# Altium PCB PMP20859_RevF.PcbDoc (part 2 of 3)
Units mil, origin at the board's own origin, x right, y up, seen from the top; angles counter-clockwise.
Board outline 5000 x 4200 mil, 4 copper layers (Top Layer, Signal Layer 1, Signal Layer 2, Bottom Layer), stack 61.2 mil thick; 264 components, 163 nets, 897 pads, 223 vias.
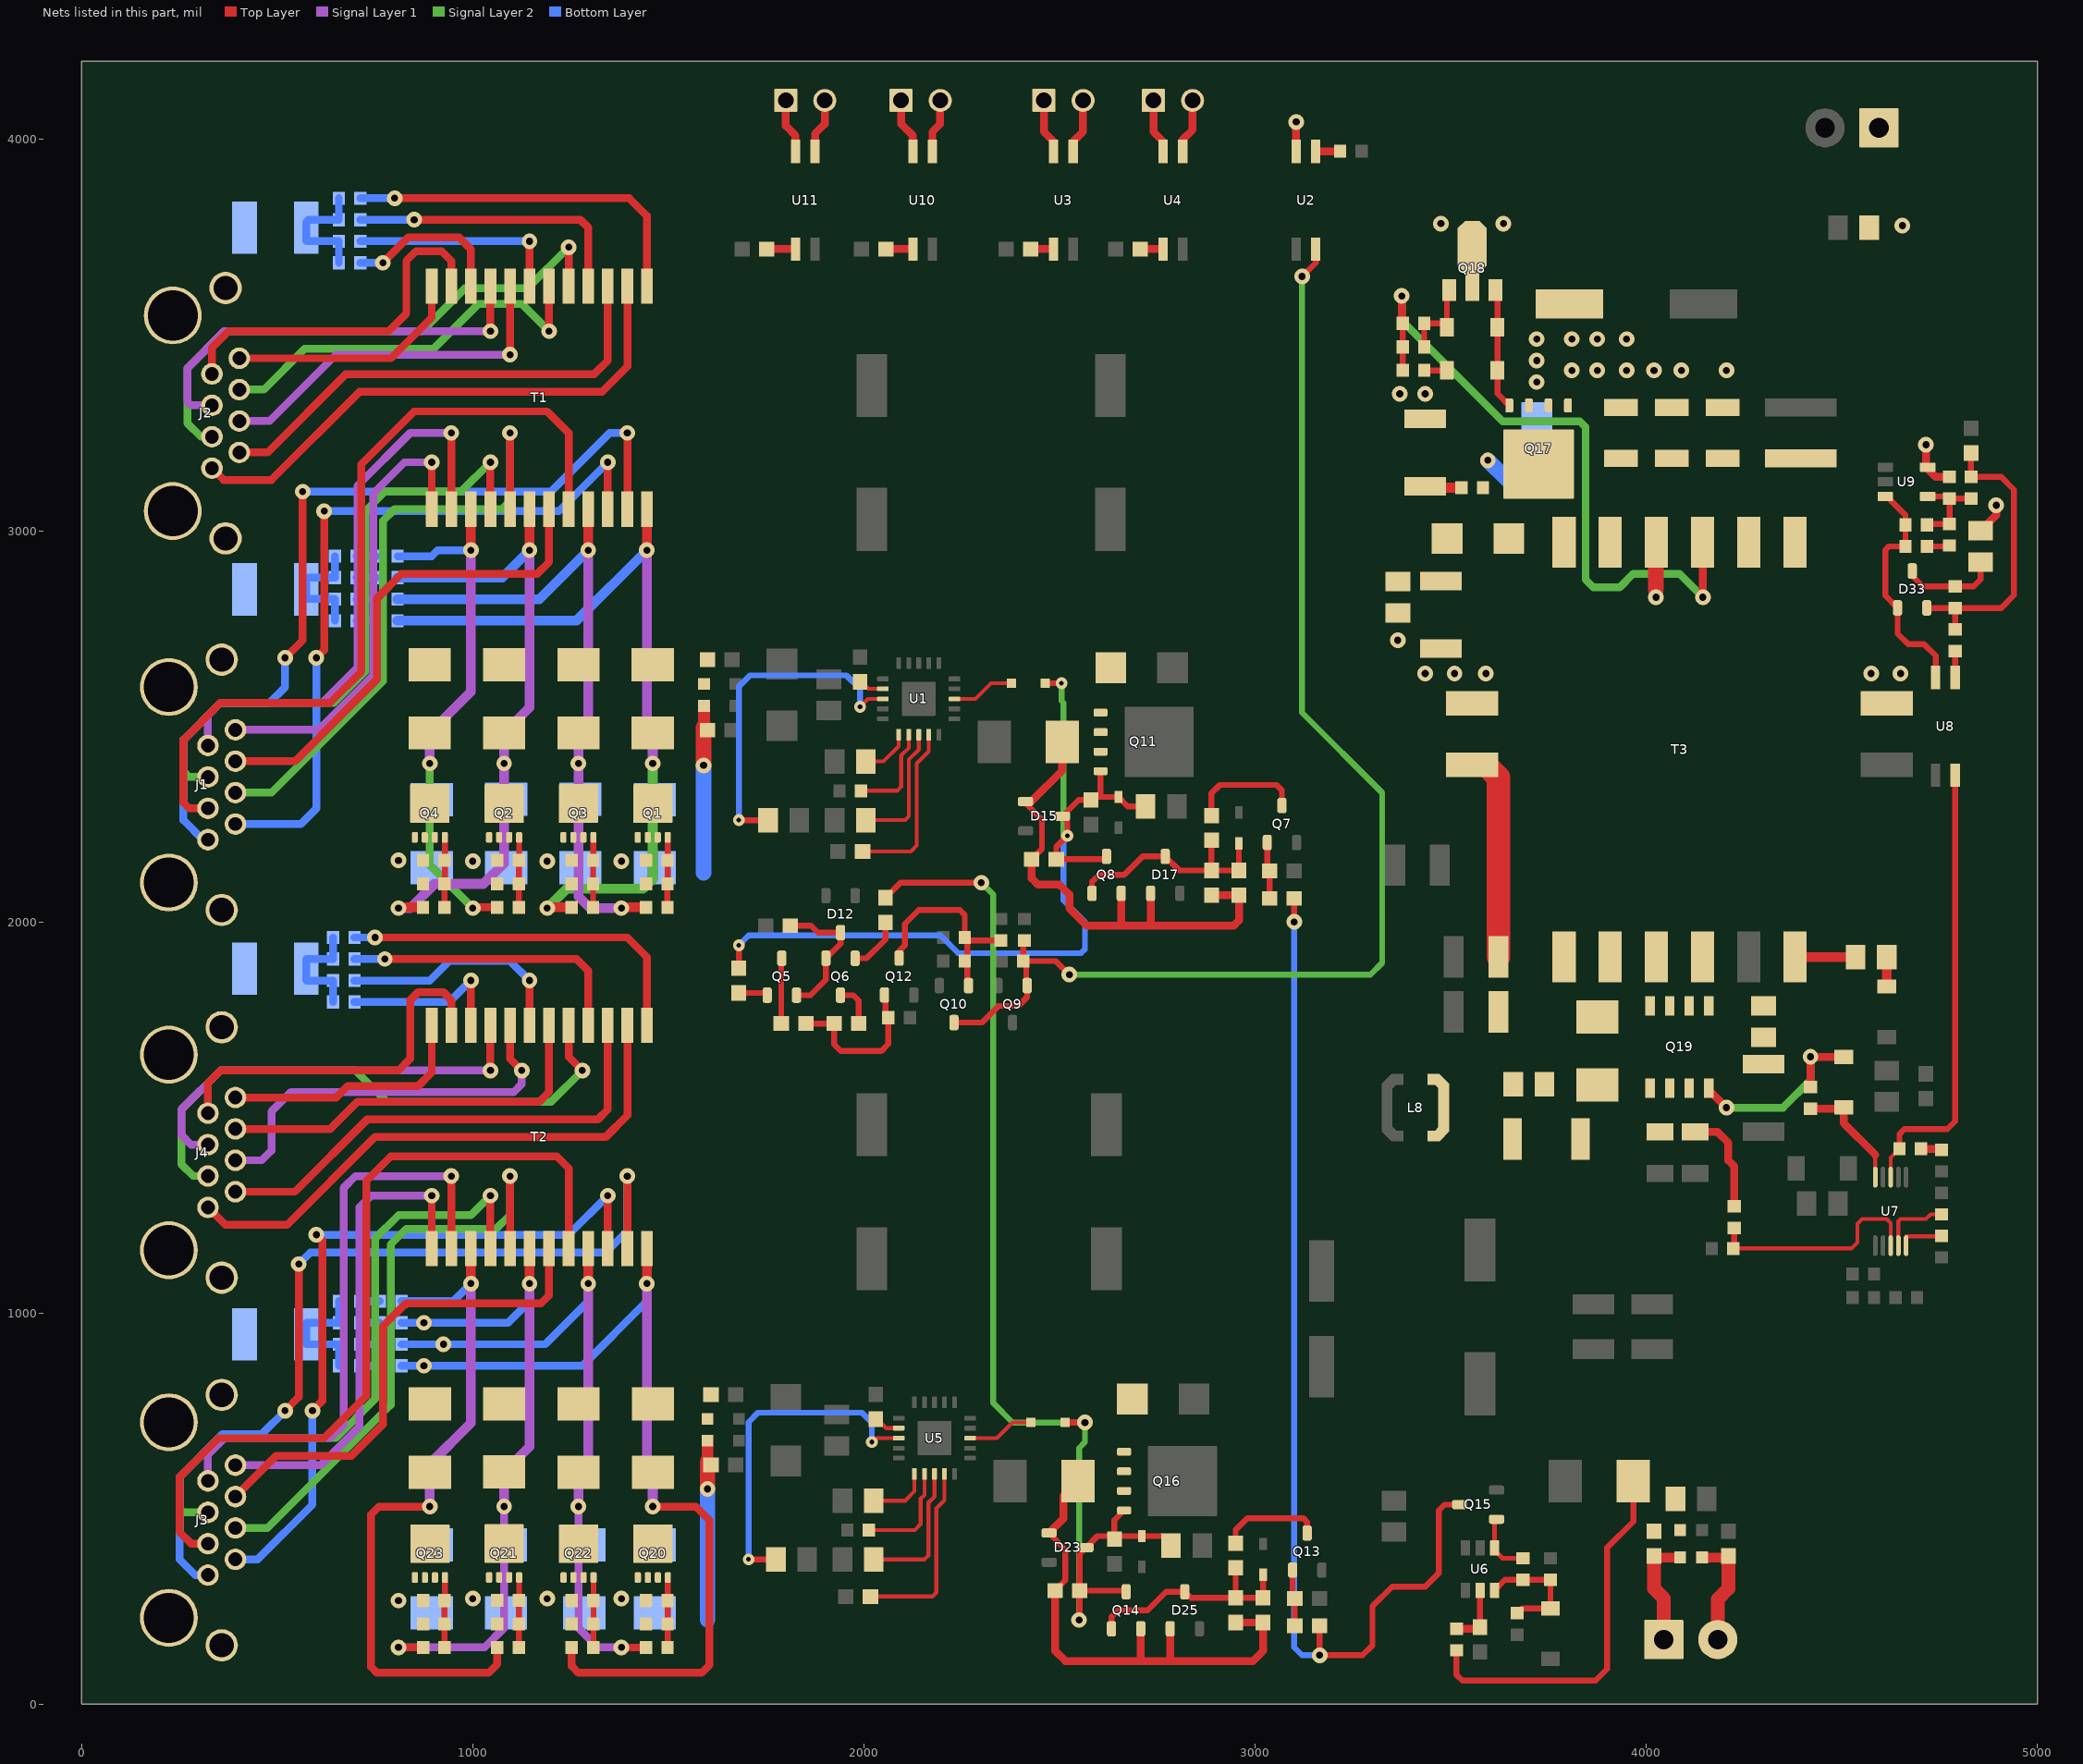
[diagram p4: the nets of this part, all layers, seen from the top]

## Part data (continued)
Q8 Q9 Q10 Q12 Q14 Q15: library part CMP-0000947-2, "MOSFET, N-CH, 100 V, 0.17 A, SOT-23", Alternate Manufacturer=None, Manufacturer="Fairchild Semiconductor", Supplier Part Number 1=BSS123NCT-ND, Value1=1, Value2="1.8 nC"
Q11 Q16: library part CMP-0000962-2, "MOSFET, N-CH, 100 V, 10 A, DQJ0008A (VSONP-8)", Alternate Manufacturer=None, Manufacturer="Texas Instruments", Value2="17 nC"
Q17: library part CMP-0000708-1, "MOSFET, N-CH, 40 V, 15 A, DQJ0008A (VSONP-8)", Alternate Manufacturer=None, Manufacturer="Texas Instruments", Supplier Part Number 1=296-30572-1-ND, Value1=0.009, Value2="7.7 nC"
Q18: library part CMP-0000356-2, "Transistor, PNP, 60 V, 0.6 A, AEC-Q101, SOT-89", Manufacturer="Diodes Inc.", Supplier Part Number 1=DXT2907ADICT-ND, Value1="0.6 A", Value2=300
Q19: library part CMP-0001058-1, "MOSFET, N-CH, 150 V, 4.6 A, PQFN08A", Alternate Manufacturer=None, Manufacturer="Fairchild Semiconductor", Supplier Part Number 1=FDMS86252CT-ND, Value1=0, Value2="11 nC"
R1 R2 R7 R12 R13 R14 R15 R16 R17 R18 R23 R28 R29 R30 R31 R32: library part CMP-0022590-4, "RES, 75.0, 1%, 0.1 W, AEC-Q200 Grade 0, 0603", Manufacturer=Vishay-Dale, PartNumber=CRCW060375R0FKEA, Power_W=100mW, Supplier Part Number 1=541-75.0HCT-ND, TempCo="100 ppm/C", Tolerance_%=1%, Value2=0.1W, Value_Code=75R0, ValueDisplayed=75.0
R3 R4 R5 R6 R19 R20 R21 R22: library part CMP-0022138-4, "RES, 1.00 M, 1%, 0.1 W, AEC-Q200 Grade 0, 0603", Manufacturer=Vishay-Dale, PartNumber=CRCW06031M00FKEA, Power_W=100mW, Supplier Part Number 1=541-1.00MHCT-ND, TempCo="100 ppm/C", Tolerance_%=1%, Value2=0.1W, Value_Code=1M00, ValueDisplayed=1.00M
R8 R9 R10 R11 R24 R25 R26 R27: library part CMP-0022224-4, "RES, 232 k, 1%, 0.1 W, AEC-Q200 Grade 0, 0603", Manufacturer=Vishay-Dale, PartNumber=CRCW0603232KFKEA, Power_W=100mW, Supplier Part Number 1=541-232KHCT-ND, TempCo="100 ppm/C", Tolerance_%=1%, Value2=0.1W, Value_Code=232k
R33 R74: library part CMP-0022204-4, "RES, 20.0 k, 1%, 0.1 W, AEC-Q200 Grade 0, 0603", Manufacturer=Vishay-Dale, PartNumber=CRCW060320K0FKEA, Power_W=100mW, Supplier Part Number 1=541-20.0KHCT-ND, TempCo="100 ppm/C", Tolerance_%=1%, Value2=0.1W, Value_Code=20k0, ValueDisplayed=20.0k
R34 R53 R55 R57 R69 R96 R97: library part CMP-0021998-4, "RES, 10.0 k, 1%, 0.1 W, AEC-Q200 Grade 0, 0603", Manufacturer=Vishay-Dale, PartNumber=CRCW060310K0FKEA, Power_W=100mW, Supplier Part Number 1=541-10.0KHCT-ND, TempCo="100 ppm/C", Tolerance_%=1%, Value2=0.1W, Value_Code=10k0, ValueDisplayed=10.0k
R35 R62: library part CMP-0022254-4, "RES, 27.4 k, 1%, 0.1 W, AEC-Q200 Grade 0, 0603", Manufacturer=Vishay-Dale, PartNumber=CRCW060327K4FKEA, Power_W=100mW, Supplier Part Number 1=541-27.4KHCT-ND, TempCo="100 ppm/C", Tolerance_%=1%, Value2=0.1W, Value_Code=27k4, ValueDisplayed=27.4k
R36 R38 R58 R59: library part CMP-0023050-5, "RES, 35.7 k, 1%, 0.1 W, 0603", Manufacturer=Yageo, Power_W=100mW, Supplier Part Number 1=311-35.7KHRCT-ND, TempCo="100 ppm/C", Tolerance_%=1%, Value2=0.1W, Value_Code=35k7, ValueDisplayed=35.7k
R37 R40 R41 R43 R61 R66 R76 R82: library part CMP-0021990-4, "RES, 100 k, 1%, 0.1 W, AEC-Q200 Grade 0, 0603", Manufacturer=Vishay-Dale, PartNumber=CRCW0603100KFKEA, Power_W=100mW, Supplier Part Number 1=541-100KHCT-ND, TempCo="100 ppm/C", Tolerance_%=1%, Value2=0.1W, Value_Code=100k
R39 R65: library part CMP-0022040-4, "RES, 137 k, 1%, 0.1 W, AEC-Q200 Grade 0, 0603", Manufacturer=Vishay-Dale, PartNumber=CRCW0603137KFKEA, Power_W=100mW, Supplier Part Number 1=541-137KHCT-ND, TempCo="100 ppm/C", Tolerance_%=1%, Value2=0.1W, Value_Code=137k
R42 R67: library part CMP-0022532-4, "RES, 60.4 k, 1%, 0.1 W, AEC-Q200 Grade 0, 0603", Manufacturer=Vishay-Dale, Power_W=100mW, Supplier Part Number 1=541-60.4KHCT-ND, TempCo="100 ppm/C", Tolerance_%=1%, Value2=0.1W, Value_Code=60k4, ValueDisplayed=60.4k
R44 R45: library part CMP-0022133-4, "RES, 1.78 k, 1%, 0.1 W, AEC-Q200 Grade 0, 0603", Manufacturer=Vishay-Dale, PartNumber=CRCW06031K78FKEA, Power_W=100mW, Supplier Part Number 1=541-1.78KHCT-ND, TempCo="100 ppm/C", Tolerance_%=1%, Value2=0.1W, Value_Code=1k78, ValueDisplayed=1.78k
R47 R71: library part CMP-0021376-3, "RES, 63.4, 1%, 0.125 W, AEC-Q200 Grade 0, 0805", Manufacturer=Vishay-Dale, PartNumber=CRCW080563R4FKEA, Power_W=125mW, Supplier Part Number 1=541-63.4CCT-ND, TempCo="100 ppm/C", Tolerance_%=1%, Value2=0.125W, Value_Code=63R4, ValueDisplayed=63.4
R48 R72: library part CMP-0020959-3, "RES, 1.21 k, 1%, 0.125 W, AEC-Q200 Grade 0, 0805", Manufacturer=Vishay-Dale, Power_W=125mW, Supplier Part Number 1=541-1.21KCCT-ND, TempCo="100 ppm/C", Tolerance_%=1%, Value2=0.125W, Value_Code=1k21, ValueDisplayed=1.21k
R49 R52: library part CMP-0022426-4, "RES, 44.2 k, 1%, 0.1 W, AEC-Q200 Grade 0, 0603", Manufacturer=Vishay-Dale, PartNumber=CRCW060344K2FKEA, Power_W=100mW, Supplier Part Number 1=541-44.2KHCT-ND, TempCo="100 ppm/C", Tolerance_%=1%, Value2=0.1W, Value_Code=44k2, ValueDisplayed=44.2k
R50 R70: library part CMP-0020476-3, "RES, 1.3 k, 5%, 0.125 W, AEC-Q200 Grade 0, 0805", Manufacturer=Vishay-Dale, PartNumber=CRCW08051K30JNEA, Power_W=125mW, Supplier Part Number 1=541-1.3KACT-ND, TempCo="200 ppm/C", Tolerance_%=5%, Value2=0.125W, Value_Code=1k30, ValueDisplayed=1.3k
R54 R75: library part CMP-0022447-4, "RES, 49.9 k, 1%, 0.1 W, AEC-Q200 Grade 0, 0603", Manufacturer=Vishay-Dale, PartNumber=CRCW060349K9FKEA, Power_W=100mW, Supplier Part Number 1=541-49.9KHCT-ND, TempCo="100 ppm/C", Tolerance_%=1%, Value2=0.1W, Value_Code=49k9, ValueDisplayed=49.9k
R56 R98: library part CMP-0022109-5, "RES, 1.00 k, 1%, 0.1 W, AEC-Q200 Grade 0, 0603", Manufacturer=Vishay-Dale, PartNumber=CRCW06031K00FKEA, Power_W=100mW, Supplier Part Number 1=541-1.00KHCT-ND, TempCo="100 ppm/C", Tolerance_%=1%, Value2=0.1W, Value_Code=1k00, ValueDisplayed=1.00k
R60: library part CMP-0021998-4, "RES, 10.0 k, 1%, 0.1 W, AEC-Q200 Grade 0, 0603", Manufacturer=Vishay-Dale, Power_W=100mW, Supplier Part Number 1=541-10.0KHCT-ND, TempCo="100 ppm/C", Tolerance_%=1%, Value2=0.1W, Value_Code=10k0, ValueDisplayed=10.0k
R77: library part CMP-0022110-4, "RES, 1.02 k, 1%, 0.1 W, AEC-Q200 Grade 0, 0603", Manufacturer=Vishay-Dale, PartNumber=CRCW06031K02FKEA, Power_W=100mW, Supplier Part Number 1=541-1.02KHCT-ND, TempCo="100 ppm/C", Tolerance_%=1%, Value2=0.1W, Value_Code=1k02, ValueDisplayed=1.02k
R78: library part CMP-0016116-3, "RES, 30 k, 5%, 0.75 W, AEC-Q200 Grade 0, 2010", Manufacturer=Vishay-Dale, PartNumber=CRCW201030K0JNEF, Power_W=750mW, Supplier Part Number 1=541-30KWCT-ND, TempCo="200 ppm/C", Tolerance_%=5%, Value2=0.75W, Value_Code=30k0, ValueDisplayed=30k
R79: library part CMP-0016106-3, "RES, 2.0 k, 5%, 0.75 W, AEC-Q200 Grade 0, 2010", Manufacturer=Vishay-Dale, PartNumber=CRCW20102K00JNEF, Power_W=750mW, Supplier Part Number 1=541-2.0KWCT-ND, TempCo="200 ppm/C", Tolerance_%=5%, Value2=0.75W, Value_Code=2k00, ValueDisplayed=2.0k
R80: library part CMP-0025821-4, "RES, 4.7, 5%, 0.1 W, AEC-Q200 Grade 0, 0603", Manufacturer=Vishay-Dale, PartNumber=CRCW06034R70JNEA, Power_W=100mW, Supplier Part Number 1=541-4.7GCT-ND, TempCo="200 ppm/C", Tolerance_%=5%, Value2=0.1W, Value_Code=4R70, ValueDisplayed=4.7
R81: library part CMP-0020497-3, "RES, 20, 5%, 0.125 W, AEC-Q200 Grade 0, 0805", Manufacturer=Vishay-Dale, PartNumber=CRCW080520R0JNEA, Power_W=125mW, Supplier Part Number 1=541-20ACT-ND, TempCo="200 ppm/C", Tolerance_%=5%, Value2=0.125W, Value_Code=20R0, ValueDisplayed=20
R84: library part CMP-0022458-4, "RES, 4.99 k, 1%, 0.1 W, AEC-Q200 Grade 0, 0603", Manufacturer=Vishay-Dale, PartNumber=CRCW06034K99FKEA, Power_W=100mW, Supplier Part Number 1=541-4.99KHCT-ND, TempCo="100 ppm/C", Tolerance_%=1%, Value2=0.1W, Value_Code=4k99, ValueDisplayed=4.99k
R85: library part CMP-0016136-3, "RES, 3.3, 5%, 0.75 W, AEC-Q200 Grade 0, 2010", Manufacturer=Vishay-Dale, PartNumber=CRCW20103R30JNEF, Power_W=750mW, Supplier Part Number 1=541-3.3WCT-ND, TempCo="200 ppm/C", Tolerance_%=5%, Value2=0.75W, Value_Code=3R30, ValueDisplayed=3.3
R86: library part CMP-0022381-4, "RES, 3.83 k, 1%, 0.1 W, AEC-Q200 Grade 0, 0603", Manufacturer=Vishay-Dale, PartNumber=CRCW06033K83FKEA, Power_W=100mW, Supplier Part Number 1=541-3.83KHCT-ND, TempCo="100 ppm/C", Tolerance_%=1%, Value2=0.1W, Value_Code=3k83, ValueDisplayed=3.83k
R87: library part CMP-0022242-4, "RES, 25.5 k, 1%, 0.1 W, AEC-Q200 Grade 0, 0603", Manufacturer=Vishay-Dale, PartNumber=CRCW060325K5FKEA, Power_W=100mW, Supplier Part Number 1=541-25.5KHCT-ND, TempCo="100 ppm/C", Tolerance_%=1%, Value2=0.1W, Value_Code=25k5, ValueDisplayed=25.5k
R88: library part CMP-0022448-4, "RES, 49.9, 1%, 0.1 W, AEC-Q200 Grade 0, 0603", Manufacturer=Vishay-Dale, PartNumber=CRCW060349R9FKEA, Power_W=100mW, Supplier Part Number 1=541-49.9HCT-ND, TempCo="100 ppm/C", Tolerance_%=1%, Value2=0.1W, Value_Code=49R9, ValueDisplayed=49.9
R89: library part CMP-0022588-5, "RES, 750, 1%, 0.1 W, AEC-Q200 Grade 0, 0603", Manufacturer=Vishay-Dale, PartNumber=CRCW0603750RFKEA, Power_W=100mW, Supplier Part Number 1=541-750HCT-ND, TempCo="100 ppm/C", Tolerance_%=1%, Value2=0.1W, Value_Code=750R, ValueDisplayed=750
R90: library part CMP-0016178-3, "RES, 75, 5%, 0.75 W, AEC-Q200 Grade 0, 2010", Manufacturer=Vishay-Dale, PartNumber=CRCW201075R0JNEF, Power_W=750mW, Supplier Part Number 1=541-75.0WCT-ND, TempCo="200 ppm/C", Tolerance_%=5%, Value2=0.75W, Value_Code=75R0, ValueDisplayed=75
R91: library part CMP-0022337-5, "RES, 332, 1%, 0.1 W, AEC-Q200 Grade 0, 0603", Manufacturer=Vishay-Dale, PartNumber=CRCW0603332RFKEA, Power_W=100mW, Supplier Part Number 1=541-332HCT-ND, TempCo="100 ppm/C", Tolerance_%=1%, Value2=0.1W, Value_Code=332R, ValueDisplayed=332
R92: library part CMP-0025697-4, "RES, 0, 5%, 0.1 W, AEC-Q200 Grade 0, 0603", Manufacturer=Vishay-Dale, PartNumber=CRCW06030000Z0EA, Power_W=100mW, Supplier Part Number 1=541-0.0GCT-ND, TempCo="200 ppm/C", Tolerance_%=5%, Value2=0.1W, Value_Code=0000, ValueDisplayed=0
R93 R94: library part CMP-0017787-2, "RES, 0.27, 1%, 0.25 W, 1206", Manufacturer=Panasonic, PartNumber=ERJ-8RQFR27V, Power_W=250mW, Supplier Part Number 1=P.27RCT-ND, TempCo="250 ppm/C", Tolerance_%=1%, Value2=0.25W, Value_Code=R270, ValueDisplayed=0.27
R95: library part CMP-0022547-5, "RES, 665, 1%, 0.1 W, AEC-Q200 Grade 0, 0603", Manufacturer=Vishay-Dale, PartNumber=CRCW0603665RFKEA, Power_W=100mW, Supplier Part Number 1=541-665HCT-ND, TempCo="100 ppm/C", Tolerance_%=1%, Value2=0.1W, Value_Code=665R, ValueDisplayed=665
R99: library part CMP-0022374-4, "RES, 3.24 k, 1%, 0.1 W, AEC-Q200 Grade 0, 0603", Manufacturer=Vishay-Dale, PartNumber=CRCW06033K24FKEA, Power_W=100mW, Supplier Part Number 1=541-3.24KHCT-ND, TempCo="100 ppm/C", Tolerance_%=1%, Value2=0.1W, Value_Code=3k24, ValueDisplayed=3.24k
R100 R101: library part CMP-0022324-4, "RES, 30.1 k, 1%, 0.1 W, AEC-Q200 Grade 0, 0603", Manufacturer=Vishay-Dale, PartNumber=CRCW060330K1FKEA, Power_W=100mW, Supplier Part Number 1=541-30.1KHCT-ND, TempCo="100 ppm/C", Tolerance_%=1%, Value2=0.1W, Value_Code=30k1, ValueDisplayed=30.1k
T1 T2: library part CMP-0030597-1, "Transformer, 350 uH, SMT", Manufacturer="Wurth Elektronik", ValueDisplayed=350uH
T3: library part CMP-0030440-2, "Transformer, 35 uH, SMT", Manufacturer="Pulse Engineering", ValueDisplayed=35uH
U1 U5: library part CMP-0013755-3, "IEEE 802.3bt PoE High-Power PD Interface with Automatic MPS & Autoclass, RGW0020B (VQFN-20)", Alternate Manufacturer="Texas Instruments", Alternate PartNumber=TPS2372-3RGWT, Operating Temperature Range="-40 to 125 C"
U2 U3 U4 U8 U10 U11: library part CMP-0006164-3, "Optocoupler, 3.75 kV, 80-160% CTR, SMT", Manufacturer="Fairchild Semiconductor", Supplier Part Number 1=HMHA2801A-ND, Voltage_Isolation_Vrms=3.75kV
U6: library part CMP-0032355-1, "Low Quiescent Current, Programmable-Delay Supervisory Circuit, 1 Supply Monitored, -40 to 125 degC, 6-pin SOT-23 (DBV), Green (RoHS & no Sb/Br)", Manufacturer="Texas Instruments", Rating=Catalog, Threshold Voltage 1 (typ)(Typ)(V)=Adjustable
U7: library part CMP-0066105-1, "13-100V Wide Vin, Current Mode PWM Boost Controller, DGS0010A (VSSOP-10)", Alternate Manufacturer="Texas Instruments"
U9: library part CMP-0032952-1, "Low Voltage Adjustable Precision Shunt Regulator, 39 ppm / degC, 15 mA, -40 to 85 degC, 5-pin SOT-23 (DBV), Green (RoHS & no Sb/Br)", Manufacturer="Texas Instruments", Rating=Catalog, Temp Coeff(Max)(ppm/ degree C)=129, Temp Coeff(Typ)(ppm/ degree C)=39

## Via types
v1: diameter 40, hole 18, Top Layer to Bottom Layer, 185 vias
v2: diameter 30, hole 12, Top Layer to Bottom Layer, 28 vias
v3: diameter 19.68, hole 7.87, Top Layer to Bottom Layer, 10 vias

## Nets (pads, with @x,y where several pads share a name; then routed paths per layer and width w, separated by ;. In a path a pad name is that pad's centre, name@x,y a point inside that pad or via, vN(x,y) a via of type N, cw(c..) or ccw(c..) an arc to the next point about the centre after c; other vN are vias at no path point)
AUX: C32.1 C33.1 D18.2 L5.2 R76.2 | length 973.8
  Top Layer w15: R76.2@3515,137.44 3515,75 3530,60 3870,60 3900,90 3900,400 3967.01,467.01 D18.2@3967.01,570
AUX_OUT: Q15.3 R39.2 R65.2 | length 2732.6
  Top Layer w15: v1(3100,2000) 3100.14,2000.14 R39.2@3100.14,2060 ; R65.2@3165,199.74 v1(3165,125) 3275,125 3300,150 3300,250 3350,300 3435,300 3470,335 3470,495 3485,510 Q15.3@3522.76,510
  Bottom Layer w15: v1(3100,2000) 3100,145 3120,125 v1(3165,125)
BSVG: C7.1 C12.2 C19.1 C24.2 J1.9 J1.10 J1.11 J1.12 J2.9 J2.10 J2.11 J2.12 J3.9 J3.10 J3.11 J3.12 J4.9 J4.10 J4.11 J4.12
GND: C41.2 C42.1 C43.2 C44.2 C45.2 C46.2 C50.2 C57.2 C67.2 D43.2 J5.2 J6.2 J8.1 J9.2 J10.2 Q17.1 Q17.2 Q17.3 Q18.2 Q18.4 R79.2 R85.1 R99.1 T3.10 U2.2 U3.3 U4.3 U9.5 U10.3 U11.3 | length 962.2
  Top Layer w20: U11.3@1875,3970 1875,4015 1900,4040 J10.2@1900,4100 ; U10.3@2175,3970 2175,4020 2195,4040 J9.2@2195,4100 ; U3.3@2535,3970 2535,3995 2560,4020 J5.2@2560,4100 ; U4.3@2815,3970 2815,4000 2840,4025 J6.2@2840,4100 ; U2.2@3105,3970 v1(3105,4045) ; v1@4715.51,3219.49 4715.51,3162.4 4740.35,3137.56 R99.1@4775.31,3137.56 ; C67.2@4855,3000 4895,3040 v1(4895,3065)
  Top Layer w40: 4025,2850 T3.10@4025,2969.07
  other v1: 3435,2635 3510,2635 3590,2635 4575,2635 4650,2635 3365,2720 4025,2830 4715,3220 3370,3350 3435,3350 3720,3380 3810,3410 3875,3410 3950,3410 4020,3410 4090,3410 4205,3410 3720,3435 3720,3490 3810,3490 3875,3490 3950,3490 4655,3780 3475,3785 3635,3785
NetC1_1: C1.1 D1.1 D2.1 D3.1 D4.1 L1.1
NetC1_2: C1.2 C3.2 C4.2 C5.2 C6.2 D35.2 D36.2 D37.2 D38.2 L2.1 Q1.1 Q1.2 Q1.3 Q2.1 Q2.2 Q2.3 Q3.1 Q3.2 Q3.3 Q4.1 Q4.2 Q4.3 R8.1 R9.1 R10.1 R11.1 | length 427.5
  Top Layer w30: L2.1@1591.32,2498.5 C1.2@1591.32,2552
  Top Layer w40: v1(1590,2400) 1590,2497.18 L2.1@1591.32,2498.5
  Bottom Layer w40: 1590,2125 v1(1590,2400)
  other v1: 1000,2155 1190,2155 1380,2155 810,2157.11
NetC3_1: C3.1 Q1.4 R3.2 R8.2 | length 179.3
  Top Layer w15: R3.2@1497.56,2037.11 R8.2@1497.56,2097.11 1498.39,2097.93 Q1.4@1498.39,2216.08
NetC4_1: C4.1 Q3.4 R4.2 R9.2 | length 160.1
  Top Layer w15: 1307.56,2056.28 R9.2@1307.56,2097.11 C4.1@1307.56,2157.11 1308.39,2157.93 Q3.4@1308.39,2216.08
NetC5_1: C5.1 Q2.4 R5.2 R10.2 | length 178.6
  Top Layer w15: R5.2@1118.05,2037.6 1118.05,2157.6 1118.39,2157.93 Q2.4@1118.39,2216.08
NetC6_1: C6.1 Q4.4 R6.2 R11.2 | length 179.3
  Top Layer w15: R6.2@927.56,2037.11 R11.2@927.56,2097.11 928.39,2097.93 Q4.4@928.39,2216.08
NetC7_2: C7.2 R1.1 R2.1 R7.1 R12.1 | length 328
  Bottom Layer w20: R12.1@657.44,3685 R7.1@657.44,3740 575,3740 573.74,3741.26 C7.2@573.74,3775 573.74,3788.74 580,3795 R2.1@657.44,3795 R1.1@657.44,3850
NetC8_2: C8.2 R13.2 | length 49.9
  Bottom Layer w20: R13.2@702.56,2770 C8.2@752.44,2770
NetC9_2: C9.2 R14.2 | length 49.9
  Bottom Layer w20: R14.2@702.56,2825 C9.2@752.44,2825
NetC10_2: C10.2 R15.2 | length 49.9
  Bottom Layer w20: R15.2@702.56,2880 C10.2@752.44,2880
NetC11_2: C11.2 R16.2 | length 49.9
  Bottom Layer w20: R16.2@702.56,2935 C11.2@752.44,2935
NetC12_1: C12.1 R13.1 R14.1 R15.1 R16.1 | length 307.7
  Bottom Layer w20: R14.1@646.18,2826.26 573.74,2826.26 C12.1@573.74,2850 573.74,2876.26 577.48,2880 R15.1@647.44,2880 R16.1@647.44,2935 ; R13.1@647.44,2770 R14.1@647.44,2825
NetC13_1: C13.1 D5.1 D6.1 D7.1 D8.1 L3.1
NetC13_2: C13.2 C15.2 C16.2 C17.2 C18.2 D39.2 D40.2 D41.2 D42.2 L4.1 Q20.1 Q20.2 Q20.3 Q21.1 Q21.2 Q21.3 Q22.1 Q22.2 Q22.3 Q23.1 Q23.2 Q23.3 R24.1 R25.1 R26.1 R27.1 | length 458.4
  Top Layer w30: L4.1@1600.32,619.8 C13.2@1600.32,673.3
  Top Layer w40: v1(1600,550) 1600,619.49 L4.1@1600.32,619.8
  Bottom Layer w40: 1600,215 v1(1600,550)
  other v1: 810,264.68 1000,269.68 1190,269.68 1380,269.68
NetC15_1: C15.1 Q20.4 R19.2 R24.2 | length 178.1
  Top Layer w15: R19.2@1498.71,145.51 Q20.4@1498.71,323.66
NetC16_1: C16.1 Q22.4 R20.2 R25.2 | length 178.1
  Top Layer w15: R20.2@1308.71,145.51 Q22.4@1308.71,323.66
NetC17_1: C17.1 Q21.4 R21.2 R26.2 | length 179.3
  Top Layer w15: R21.2@1117.56,145 R26.2@1117.56,205 C17.1@1117.56,265 1118.39,265.82 Q21.4@1118.39,323.97
NetC18_1: C18.1 Q23.4 R22.2 R27.2 | length 179.3
  Top Layer w15: R22.2@927.88,144.68 R27.2@927.88,204.68 C18.1@927.88,264.68 928.71,265.51 Q23.4@928.71,323.66
NetC19_2: C19.2 R17.1 R18.1 R23.1 R28.1 | length 300.9
  Bottom Layer w20: R28.1@642.44,1795 R23.1@642.44,1850 575,1850 573.74,1851.26 C19.2@573.74,1880.31 573.74,1903.74 575,1905 R18.1@642.44,1905 R17.1@642.44,1960
NetC20_2: C20.2 R29.2 | length 49.9
  Bottom Layer w20: R29.2@712.56,865 C20.2@762.44,865
NetC21_2: C21.2 R30.2 | length 49.9
  Bottom Layer w20: R30.2@712.56,920 C21.2@762.44,920
NetC22_2: C22.2 R31.2 | length 49.9
  Bottom Layer w20: R31.2@712.56,975 C22.2@762.44,975
NetC23_2: C23.2 R32.2 | length 49.9
  Bottom Layer w20: R32.2@712.56,1030 C23.2@762.44,1030
NetC24_1: C24.1 R29.1 R30.1 R31.1 R32.1 | length 330.9
  Bottom Layer w20: R29.1@657.44,865 R30.1@657.44,920 575,920 573.74,921.26 C24.1@573.74,945 573.74,973.74 575,975 R31.1@657.44,975 R32.1@657.44,1030
NetC28_1: C28.1 C68.2 D9.2 D14.2 D15.3 Q8.3 Q11.4 R37.1 R40.1 | length 2296.6
  Top Layer w15: R40.1@1680,1881.18 v2(1680,1940) ; D14.2@2463.62,2610 v2(2505,2610) ; Q11.4@2604.96,2385 2604.96,2319.41 2588.23,2319.41 R37.1@2588.19,2319.37 ; Q8.3@2613.07,2160 C28.1@2491.81,2160 2491.81,2191.81 v2(2520,2220) 2520,2257.56 D15.3@2507.56,2270 2549.06,2311.5 R37.1@2580.32,2311.5 R37.1@2588.19,2319.37 ; C68.2@2720,2295 2674.69,2295 D9.2@2650.32,2319.37 R37.1@2588.19,2319.37
  Signal Layer 2 w15: v2(2505,2610) 2505,2565 2510,2560 v2@2510,2220
  Bottom Layer w15: v2(1680,1940) 1705,1965 2195.98,1965 2240.98,1920 2555,1920 2565,1930 2565,2000 2510,2055 v2@2510,2220
NetC28_2: C28.2 C29.2 D13.2 D15.1 D16.2 D17.1 Q8.2 Q11.1 Q11.2 Q11.3 R100.1 | length 1326.5
  Top Layer w15: D15.1@2413.07,2307.4 2413.07,2303.04 2455,2261.11 2455,2186.18 C28.2@2428.82,2160
  Top Layer w20: D15.1@2413.07,2307.4 2427.4,2307.4 2507.01,2387.01 D16.2@2507.01,2460 ; C28.2@2428.82,2160 2428.82,2111.18 2445,2095 2500,2095 2525,2070 2525,2035 2570,1990 2945,1990 2958.64,2003.64 R100.1@2958.64,2068.5 C29.2@2888.64,2068.5 ; 2657.72,1992.28 Q8.2@2657.72,2072.76 ; 2732.91,1992.09 D17.1@2732.91,2072.76
NetC29_1: C29.1 D10.2 D17.3 Q8.1 R43.1 R100.2 | length 593.1
  Top Layer w15: Q8.1@2582.91,2072.76 2582.91,2102.28 2600.63,2120 2665.58,2120 2712.83,2167.24 D17.3@2770.32,2167.24 2806.06,2131.5 C29.1@2888.64,2131.5 ; R43.1@2888.64,2208.5 C29.1@2888.64,2131.5 ; D10.2@2958.64,2200.63 R100.2@2958.64,2131.5 C29.1@2888.64,2131.5
NetC30_1: C30.1 Q10.1 Q12.3 R52.2 R55.2 | length 532.5
  Top Layer w15: Q12.3@2090,1907.24 2090,1925 2105,1940 2105,1995 2140,2030 2245,2030 2257.56,2017.44 C30.1@2257.56,1959.68 2265.12,1952.13 R52.2@2350,1952.13 ; Q10.1@2264.43,1846.77 C30.1@2264.43,1959.68
NetC34_1: C34.1 J7.1 L5.1 | length 287.4
  Top Layer w25: L5.1@4023.5,375 C34.1@4087,375
  Top Layer w35: L5.1@4020,378.5 4020,295 4045,270 J7.1@4045,165
NetC34_2: C34.2 J7.2 L6.1 | length 288.2
  Top Layer w25: C34.2@4143,375 L6.1@4206.5,375
  Top Layer w35: J7.2@4183,165 4183,268 4210,295 L6.1@4210,378.5
NetC38_2: C38.2 C39.2 D23.1 D25.1 D26.2 D34.2 Q14.2 Q16.1 Q16.2 Q16.3 R101.1 | length 1349.9
  Top Layer w15: D23.1@2473.07,437.4 2473.07,436.93 2515,395 2515,316.18 C38.2@2488.82,290
  Top Layer w20: D23.1@2473.07,437.4 2510,474.33 2510,532.68 D26.2@2547.32,570 ; C38.2@2488.82,290 2488.82,136.18 2515,110 2995,110 3020.32,135.32 R101.1@3020.32,208.5 C39.2@2950.32,208.5 ; 2707.72,112.28 Q14.2@2707.72,192.76 ; 2782.91,112.09 D25.1@2782.91,192.76
NetC39_1: C39.1 D19.2 D25.3 Q14.1 R66.1 R101.2 | length 586.9
  Top Layer w15: Q14.1@2632.91,192.76 2632.91,222.91 2650,240 2725,240 2772.24,287.24 D25.3@2820.32,287.24 2836.06,271.5 C39.1@2950.32,271.5 ; R66.1@2950.32,348.5 C39.1@2950.32,271.5 ; D19.2@3020.32,330.63 R101.2@3020.32,271.5 C39.1@2950.32,271.5
NetC40_2: C40.2 D24.1 R69.1 R74.1 U6.6 | length 316.5
  Top Layer w15: U6.6@3612.4,290.87 3638.98,317.44 R74.1@3685,317.44 R69.1@3755,317.44 D24.1@3755,244.47 3681.91,244.47 C40.2@3670,232.56
NetC41_1: C41.1 C48.1 C49.1 C52.1 L8.2 R78.2 T3.1 T3.2 | length 539.8
  Top Layer w60: C41.1@3555,2401.26 3590.43,2401.26 3622.09,2369.61 C49.1@3622.09,1910
NetC42_2: C42.2 D27.1 R79.1
NetC43_1: C43.1 C44.1 C45.1 L7.1 T3.7 T3.11
NetC52_2: C52.2 D28.1 R78.1
NetC55_1: C55.1 R80.2 R84.2 T3.9 | length 1713.1
  Top Layer w15: R80.2@3377.44,3410 R84.2@3377.44,3530
  Top Layer w20: v1(3375,3600) 3375,3532.44 R84.2@3377.44,3530 ; v1(4145,2830) T3.9@4145,2969.07
  Signal Layer 2 w20: v1(3375,3600) 3375,3537.5 3632.5,3280 3830,3280 3845,3265 3845,2875 3865,2855 3931.81,2855 3966.81,2890 4085,2890 v1(4145,2830)
NetC55_2: C55.2 D31.2 Q18.1 R84.1 | length 215.6
  Top Layer w15: C55.2@3432.56,3470 R84.1@3432.56,3530 3490,3530 D31.2@3490.54,3529.46 ; D31.2@3490.54,3520 D31.2@3490.54,3529.46 ; Q18.1@3495.95,3615.2 3490.54,3609.79 D31.2@3490.54,3529.46
NetC56_1: C56.1 R85.2 | length 89.1
  Top Layer w25: R85.2@3438.39,3110 C56.1@3527.44,3110
NetC56_2: C56.2 D27.2 D43.1 Q17.5 Q17.6 Q17.7 Q17.8 Q17.9@3725,3170.43 T3.8 T3.12 | length 145.2
  Bottom Layer w40: v1(3595,3180) 3643.74,3131.26 D43.1@3720,3131.26
NetC61_2: C61.2 U7.10 | length 108.2
  Top Layer w10: U7.10@4664.37,1178.98 4664.37,1196.06 4753.82,1196.06 C61.2@4755,1197.24
NetC62_1: C62.1 R89.2 | length 53.5
  Top Layer w20: C62.1@4702.56,1419.69 4752.56,1419.69 R89.2@4755,1417.24
NetC62_2: C62.2 U7.3 U8.4 | length 1167.4
  Top Layer w10: U7.3@4625,1340.39 4625,1397.24 C62.2@4647.44,1419.69
  Top Layer w15: C62.2@4647.44,1419.69 4647.44,1457.44 4660,1470 4770,1470 4790,1490 U8.4@4790,2375
NetC63_1: C63.1 D28.2 Q19.5 Q19.6 Q19.7 Q19.8 T3.3 T3.4
NetC63_2: C63.2 R90.2
NetC64_1: C64.1 R91.1 U7.8 | length 566.2
  Top Layer w10: C64.1@4223.05,1165 4225,1165 4525,1165 4540,1180 4540,1227.83 4552.17,1240 4615,1240 4625,1230 U7.8@4625,1178.98
  Top Layer w15: C64.1@4225,1167.44 R91.1@4225,1217.44
NetC65_1: C65.1 C66.2 R97.2 R99.2 U9.4 | length 236.7
  Top Layer w15: U9.4@4715.51,3087.6 4770.16,3087.6 R99.2@4775.31,3082.44 ; C65.1@4720.43,3017.56 C66.2@4775.31,3017.56 R99.2@4775.31,3082.44 ; R97.2@4830.31,3082.44 R99.2@4775.31,3082.44
NetC65_2: C65.2 D33.1 R98.2 U8.2 U9.3 | length 605.6
  Top Layer w15: U9.3@4615.12,3087.6 4662.76,3039.96 C65.2@4662.76,3015 R98.2@4662.76,2960 4620,2960 4611.1,2951.1 4611.1,2834.25 D33.1@4642.6,2802.76 4642.6,2737.4 4670,2710 4710,2710 4740,2680 U8.2@4740,2625
NetC66_1: C66.1 R98.1 | length 55
  Top Layer w15: R98.1@4717.87,2960 C66.1@4772.87,2960
NetC67_1: C67.1 D33.3 R96.1 | length 251.2
  Top Layer w15: D33.3@4680,2897.24 4680,2884.43 4706.87,2857.56 R96.1@4790,2857.56 4837.56,2857.56 4855,2875 C67.1@4855,2920
NetD12_3: D12.3 Q5.2 Q6.2 R33.1 | length 363.6
  Top Layer w15: R33.1@1811.5,1990 1864.96,1990 1882.52,1972.44 D12.3@1940,1972.44 1940,1944.33 Q6.2@1902.6,1906.93 1902.6,1851.5 1863.54,1812.44 Q5.2@1827.4,1812.44
NetD14_1: D14.1 U1.13 | length 162
  Top Layer w10: U1.13@2231.54,2570 2285,2570 2325,2610 D14.1@2377.01,2610
NetD22_1: D22.1 U5.13 | length 171.7
  Top Layer w10: U5.13@2271.85,680 2340,680 2380,720 D22.1@2427.01,720
NetD29_1: D29.1 D31.1 Q17.4 Q18.3 | length 310
  Top Layer w15: Q18.3@3614.06,3615.2 3619.47,3609.79 D31.1@3619.47,3520 D29.1@3619.47,3410 3619.47,3350.57 Q17.4@3650,3320.04
NetD29_2: D29.2 R80.1 | length 58
  Top Layer w15: R80.1@3432.56,3410 D29.2@3490.54,3410
NetD30_2: D30.2 R81.1 | length 75.5
  Top Layer w25: D30.2@4615,1834.47 R81.1@4615,1910
NetD32_1: D32.1 R88.2 U7.5 | length 304.8
  Top Layer w10: U7.5@4585.63,1340.39 4585.63,1404.37
  Top Layer w20: R88.2@4420,1522.44 4501.91,1522.44 D32.1@4505,1525.53 4505,1485 4585.63,1404.37
NetD32_2: D32.2 Q19.4 R88.1 | length 534.4
  Top Layer w20: Q19.4@4160,1574.88 4160,1570 v1(4205,1525) ; R88.1@4420,1577.56 v1(4420,1655) D32.2@4504.47,1655
  Signal Layer 2 w20: v1(4205,1525) 4350,1525 4420,1595 v1(4420,1655)
NetD33_2: D33.2 R92.2 R95.2 R96.2 R97.1 | length 748.7
  Top Layer w15: D33.2@4717.72,2802.44 R96.2@4790,2802.44 ; R95.2@4790,2747.56 R96.2@4790,2802.44 ; R92.2@4830.31,3202.44 R97.1@4830.31,3137.56 4907.44,3137.56 4940,3105 4940,2835 4907.44,2802.44 R96.2@4790,2802.44
NetJ1_1: J1.1 T1.23 | length 2212.9
  Top Layer w20: v1(520,2675) 565,2720 v1(565,3100) ; T1.23@1395,3052.5 v1(1395,3250)
  Bottom Layer w20: J1.1@322.91,2209.84 310.16,2209.84 260,2260 260,2465 355,2560 480,2560 520,2600 v1(520,2675) ; v1(565,3100) 1200,3100 1350,3250 v1(1395,3250)
NetJ1_2: J1.2 T1.22 | length 1891.1
  Top Layer w20: v1(600,2675) 620,2695 v1(620,3050) ; T1.22@1345,3052.5 v1(1345,3175)
  Bottom Layer w20: J1.2@392.99,2250 560,2250 600,2290 v1(600,2675) ; v1(620,3050) 1220,3050 v1(1345,3175)
NetJ1_3: J1.3 T1.20 | length 2092.7
  Top Layer w20: J1.3@322.91,2290.16 274.84,2290.16 260,2305 260,2465 355,2560 635,2560 715,2640 715,3170 850,3305 1190,3305 1245,3250 T1.20@1245,3052.5
NetJ1_4: J1.4 T1.17 | length 1623.1
  Top Layer w20: T1.17@1095,3052.5 v1(1095,3250)
  Signal Layer 2 w20: J1.4@392.99,2330.32 485.32,2330.32 770,2615 770,3025 800,3055 1075,3055 1095,3075 v1(1095,3250)
NetJ1_5: J1.5 T1.16 | length 1590.7
  Top Layer w20: T1.16@1045,3052.5 v1(1045,3175)
  Signal Layer 2 w20: J1.5@322.91,2370.47 274.53,2370.47 260,2385 260,2465 355,2560 645,2560 725,2640 725,3050 774.84,3099.84 969.84,3099.84 v1(1045,3175)
NetJ1_6: J1.6 T1.19 | length 1266.7
  Top Layer w20: J1.6@392.99,2410.63 545.63,2410.63 755,2620 755,2826.95 818.05,2890 1165,2890 1195,2920 T1.19@1195,3052.5
NetJ1_7: J1.7 T1.14 | length 1468.2
  Top Layer w20: T1.14@945,3052.5 v1(945,3250)
  Signal Layer 1 w20: J1.7@322.91,2450.79 322.91,2527.91 355,2560 615,2560 705,2650 705,3115 840,3250 v1(945,3250)
NetJ1_8: J1.8 T1.13 | length 1180.2
  Top Layer w20: T1.13@895,3052.5 v1(895,3175)
  Signal Layer 1 w20: J1.8@392.99,2490.94 605.94,2490.94 745,2630 745,3095 825,3175 v1(895,3175)
NetJ2_1: J2.1 T1.2 | length 1402.1
  Top Layer w20: J2.1@332.91,3159.84 362.76,3130 485,3130 710,3355 1330,3355 1395,3420 T1.2@1395,3627.5
NetJ2_2: J2.2 T1.3 | length 1231.8
  Top Layer w20: J2.2@402.99,3200 475,3200 675,3400 1310,3400 1345,3435 T1.3@1345,3627.5
NetJ2_3: J2.3 T1.5 | length 1418.3
  Top Layer w20: T1.5@1245,3627.5 v1(1245,3725)
  Signal Layer 2 w20: J2.3@332.91,3240.16 304.84,3240.16 270,3275 270,3415 365,3510 869.84,3510 979.84,3620 1140,3620 v1(1245,3725)
NetJ2_4: J2.4 T1.8 | length 939.8
  Top Layer w20: v1(1095,3450) T1.8@1095,3627.5
  Signal Layer 1 w20: J2.4@402.99,3280.31 480.32,3280.31 650,3450 v1(1095,3450)
NetJ2_5: J2.5 T1.9 | length 1083.7
  Top Layer w20: v1(1045,3510) T1.9@1045,3627.5
  Signal Layer 1 w20: J2.5@332.91,3320.47 279.53,3320.47 270,3330 270,3415 365,3510 v1(1045,3510)
NetJ2_6: J2.6 T1.6 | length 1029.4
  Top Layer w20: v1(1195,3510) T1.6@1195,3627.5
  Signal Layer 2 w20: J2.6@402.99,3360.63 465.63,3360.63 570,3465 900,3465 1015,3580 1125,3580 v1(1195,3510)
NetJ2_7: J2.7 T1.11 | length 933.5
  Top Layer w20: J2.7@332.91,3400.79 332.91,3467.91 375,3510 785,3510 830,3555 830,3690 855,3715 920,3715 945,3690 T1.11@945,3627.5
NetJ2_8: J2.8 T1.12 | length 617.6
  Top Layer w20: J2.8@402.99,3440.94 790.94,3440.94 895,3545 T1.12@895,3627.5
NetJ3_1: J3.1 T2.23 | length 2232.3
  Top Layer w20: v1(520,750) 555,785 v1(555,1125) ; T2.23@1395,1162.5 v1(1395,1350)
  Bottom Layer w20: J3.1@322.91,329.84 290.16,329.84 250,370 250,580 360,690 460,690 v1(520,750) ; v1(555,1125) 585,1155 1340.16,1155 1395,1209.84 v1(1395,1350)
NetJ3_2: J3.2 T2.22 | length 1885.6
  Top Layer w20: v1(590,750) 615.08,775.08 615.08,1184.92 v1(600,1200) ; T2.22@1345,1162.5 v1(1345,1300)
  Bottom Layer w20: J3.2@392.99,370 450,370 590,510 v1(590,750) ; v1(600,1200) 1245,1200 v1(1345,1300)
NetJ3_3: J3.3 T2.20 | length 2102
  Top Layer w20: J3.3@322.91,410.16 279.84,410.16 250,440 250,580 350,680 620,680 727.44,787.44 727.44,1337.44 790,1400 1215,1400 1245,1370 T2.20@1245,1162.5
NetJ3_4: J3.4 T2.17 | length 1560.9
  Top Layer w20: T2.17@1095,1162.5 v1(1095,1350)
  Signal Layer 2 w20: J3.4@392.99,450.32 475.32,450.32 790,765 790,1175 830,1215 1060,1215 1095,1250 v1(1095,1350)
NetJ3_5: J3.5 T2.16 | length 1627.8
  Top Layer w20: T2.16@1045,1162.5 v1(1045,1300)
  Signal Layer 2 w20: J3.5@322.91,490.47 259.53,490.47 250,500 250,580 350,680 650,680 750,780 750,1190 810,1250 995,1250 v1(1045,1300)
NetJ3_6: J3.6 T2.19 | length 1279.4
  Top Layer w20: J3.6@392.99,530.63 497.36,635 690,635 770,715 770,965.67 829.33,1025 1175,1025 1195,1045 T2.19@1195,1162.5
NetJ3_7: J3.7 T2.14 | length 1526.1
  Top Layer w20: T2.14@945,1162.5 v1(945,1350)
  Signal Layer 1 w20: J3.7@322.91,570.79 322.91,637.91 365,680 635,680 670,715 670,1320 700,1350 v1(945,1350)
NetJ3_8: J3.8 T2.13 | length 1253
  Top Layer w20: T2.13@895,1162.5 v1(895,1300)
  Signal Layer 1 w20: J3.8@392.99,610.94 610.94,610.94 710,710 710,1270 740,1300 v1(895,1300)
NetJ4_1: J4.1 T2.2 | length 1439.1
  Top Layer w20: J4.1@322.91,1269.84 367.76,1225 525,1225 750,1450 1340,1450 1395,1505 T2.2@1395,1737.5
NetJ4_2: J4.2 T2.3 | length 1256.5
  Top Layer w20: J4.2@392.99,1310 545,1310 730,1495 1320,1495 1345,1520 T2.3@1345,1737.5
NetJ4_3: J4.3 T2.5 | length 1485
  Top Layer w20: T2.5@1245,1737.5 1245,1655 v1(1280,1620)
  Signal Layer 2 w20: J4.3@322.91,1350.16 284.84,1350.16 255,1380 255,1520 355,1620 700,1620 780,1540 1200,1540 v1(1280,1620)
NetJ4_4: J4.4 T2.8 | length 1036.2
  Top Layer w20: T2.8@1095,1737.5 1095,1650 v1(1125,1620)
  Signal Layer 1 w20: J4.4@392.99,1390.32 460.32,1390.32 485,1415 485,1515 535,1565 1105,1565 1125,1585 v1(1125,1620)
NetJ4_5: J4.5 T2.9 | length 1092
  Top Layer w20: v1(1045,1620) T2.9@1045,1737.5
  Signal Layer 1 w20: J4.5@322.91,1430.47 279.53,1430.47 255,1455 255,1520 355,1620 v1(1045,1620)
NetJ4_6: J4.6 T2.6 | length 1013.6
  Top Layer w20: J4.6@392.99,1470.63 635.63,1470.63 705,1540 1170,1540 1195,1565 T2.6@1195,1737.5
NetJ4_7: J4.7 T2.11 | length 954
  Top Layer w20: J4.7@322.91,1510.79 322.91,1587.91 355,1620 810,1620 840,1650 840,1800 860,1820 925,1820 945,1800 T2.11@945,1737.5
NetJ4_8: J4.8 T2.12 | length 651
  Top Layer w20: J4.8@392.99,1550.94 650.94,1550.94 680,1580 860,1580 895,1615 T2.12@895,1737.5
NetJ5_1: J5.1 U3.4 | length 140.4
  Top Layer w20: J5.1@2460,4100 2460,4020 2485,3995 U3.4@2485,3970
NetJ6_1: J6.1 U4.4 | length 140.4
  Top Layer w20: J6.1@2740,4100 2740,4020 2765,3995 U4.4@2765,3970
NetJ9_1: J9.1 U10.4 | length 142.4
  Top Layer w20: J9.1@2095,4100 2095,4040 2125,4010 U10.4@2125,3970
NetJ10_1: J10.1 U11.4 | length 140.4
  Top Layer w20: J10.1@1800,4100 1800,4035 1825,4010 U11.4@1825,3970
NetQ5_1: Q5.1 R40.2 | length 75
  Top Layer w15: R40.2@1680,1818.19 1746.85,1818.19 Q5.1@1752.6,1812.44
NetQ5_3: Q5.3 R44.1 | length 165.4
  Top Layer w15: R44.1@1788.5,1740 Q5.3@1788.5,1905.43
NetQ6_1: Q6.1 R41.2 | length 141
  Top Layer w15: Q6.1@1977.4,1906.93 2006.93,1906.93 2055,1955 R41.2@2055,1998.5
NetQ6_3: Q6.3 R45.2 | length 110.8
  Top Layer w15: Q6.3@1940,1812.44 1972.56,1812.44 1986.5,1798.5 R45.2@1986.5,1740
NetQ7_1: Q7.1 R34.1 R39.1 | length 145.2
  Top Layer w15: Q7.1@3031.24,2202.76 3031.24,2135.91 R34.1@3037.15,2130 R39.1@3037.15,2060
NetQ7_3: Q7.3 R43.2 | length 290.8
  Top Layer w15: R43.2@2888.64,2271.5 2888.64,2328.64 2910,2350 3055,2350 3068.64,2336.36 Q7.3@3068.64,2297.24
NetQ9_1: Q9.1 Q10.3 R49.1 R53.2 U2.4 | length 3218.8
  Top Layer w15: Q10.3@2230,1742.44 2302.26,1742.44 2344.82,1785 2395,1785 2417.4,1807.4 Q9.1@2417.4,1836.93 ; R49.1@2410,1952.13 2407.56,1949.68 R53.2@2407.56,1899.68 2490.32,1899.68 v1(2525,1865) ; Q9.1@2415,1850 R53.2@2415,1902.91 ; v1(3120,3650) 3155,3685 U2.4@3155,3720
  Signal Layer 2 w15: v1(2525,1865) 3295,1865 3325,1895 3325,2330 3120,2535 v1(3120,3650)
NetQ12_1: Q12.1 R44.2 R45.1 R57.2 | length 394
  Top Layer w15: R44.2@1851.5,1740 R45.1@1923.5,1740 1923.5,1686.5 1940,1670 2045,1670 2062.44,1687.44 R57.2@2062.44,1755 ; R57.2@2055,1757.09 Q12.1@2055,1805
NetQ13_1: Q13.1 R60.1 R65.1 | length 145.2
  Top Layer w15: Q13.1@3095.84,342.76 3095.84,275.91 R60.1@3101.75,270 R65.1@3101.75,200
NetQ13_3: Q13.3 R66.2 | length 261.4
  Top Layer w15: R66.2@2950.32,411.5 2950.32,445.32 2980,475 3124.03,475 3133.24,465.79 Q13.3@3133.24,437.24
NetQ15_1: Q15.1 R74.2 U6.1 | length 162.6
  Top Layer w12: Q15.1@3617.24,472.6 3612.4,467.76 U6.1@3612.4,399.13 3612.4,393.05 3632.89,372.56 R74.2@3685,372.56
NetQ19_1: Q19.1 Q19.2 Q19.3 R91.2 R93.2 R94.2 | length 265.3
  Top Layer w20: R94.2@4125,1463.15 4181.85,1463.15 4210,1435 4210,1390 4225,1375 R91.2@4225,1272.56
NetR1_2: R1.2 T1.1 | length 928.6
  Top Layer w20: v1(800,3850) 1400,3850 1445,3805 T1.1@1445,3627.5
  Bottom Layer w20: R1.2@712.56,3850 v1(800,3850)
NetR2_2: R2.2 T1.4 | length 738.2
  Top Layer w20: v1(850,3795) 1275,3795 1295,3775 T1.4@1295,3627.5
  Bottom Layer w20: R2.2@712.56,3795 v1(850,3795)
NetR7_2: R7.2 T1.7 | length 544.9
  Top Layer w20: T1.7@1145,3627.5 v1(1145,3740)
  Bottom Layer w20: R7.2@712.56,3740 v1(1145,3740)
NetR12_2: R12.2 T1.10 | length 414.3
  Top Layer w20: v1(770,3685) 835,3750 965,3750 995,3720 T1.10@995,3627.5
  Bottom Layer w20: R12.2@712.56,3685 v1(770,3685)
NetR17_2: R17.2 T2.1 | length 940.7
  Top Layer w20: v1(750,1960) 1395,1960 1445,1910 T2.1@1445,1737.5
  Bottom Layer w20: R17.2@697.56,1960 v1(750,1960)
NetR18_2: R18.2 T2.4 | length 747.4
  Top Layer w20: v1(775,1905) 1265,1905 1295,1875 T2.4@1295,1737.5
  Bottom Layer w20: R18.2@697.56,1905 v1(775,1905)
NetR23_2: R23.2 T2.7 | length 601.4
  Top Layer w20: T2.7@1145,1737.5 v1(1145,1850)
  Bottom Layer w20: R23.2@697.56,1850 890,1850 940,1900 1095,1900 v1(1145,1850)
NetR28_2: R28.2 T2.10 | length 432.7
  Top Layer w20: T2.10@995,1737.5 v1(995,1850)
  Bottom Layer w20: R28.2@697.56,1795 940,1795 v1(995,1850)
NetR35_1: R35.1 U1.2 | length 67.5
  Top Layer w10: R35.1@1990,2617.44 2011.85,2595.59 U1.2@2048.46,2595.59
NetR36_2: R36.2 U10.1 | length 68.5
  Top Layer w20: R36.2@2056.5,3720 U10.1@2125,3720
NetR38_2: R38.2 U11.1 | length 73.5
  Top Layer w20: R38.2@1751.5,3720 U11.1@1825,3720
NetR42_1: R42.1 U1.9 | length 440.9
  Top Layer w10: R42.1@1996.5,2180 2120,2180 2135,2195 2135,2405 2165.59,2435.59 U1.9@2165.59,2478.46
NetR47_2: R47.2 U1.3 | length 864.6
  Top Layer w10: v2(1990,2550) 2010,2570 U1.3@2048.46,2570
  Top Layer w15: v2(1680,2260) R47.2@1755,2260
  Bottom Layer w15: v2(1680,2260) 1680,2601.65 1708.35,2630 1955,2630 1990,2595 v2(1990,2550)
NetR48_2: R48.2 U1.6 | length 129.5
  Top Layer w10: R48.2@2005,2410 2050,2410 2088.82,2448.82 U1.6@2088.82,2478.46
NetR50_1: R50.1 U1.8 | length 333
  Top Layer w10: R50.1@2005,2260 2105,2260 2115,2270 2115,2415 2140,2440 U1.8@2140,2478.46
NetR54_2: R54.2 U1.7 | length 248.1
  Top Layer w10: R54.2@1992.56,2335 2085,2335 2095,2345 2095,2425 2114.41,2444.41 U1.7@2114.41,2478.46
NetR56_1: R56.1 U2.1 | length 62.4
  Top Layer w20: U2.1@3155,3970 R56.1@3217.44,3970
NetR58_2: R58.2 U3.1 | length 62.4
  Top Layer w20: R58.2@2422.56,3720 U3.1@2485,3720
NetR59_2: R59.2 U4.1 | length 62.4
  Top Layer w20: R59.2@2702.56,3720 U4.1@2765,3720
NetR62_1: R62.1 U5.2 | length 69.6
  Top Layer w10: R62.1@2030.32,732.44 2057.17,705.59 U5.2@2088.78,705.59
NetR67_1: R67.1 U5.9 | length 484.8
  Top Layer w10: R67.1@2016.5,275 2175,275 2185,285 2185,500 2205.91,520.91 U5.9@2205.91,588.46
NetR70_1: R70.1 U5.8 | length 359
  Top Layer w10: R70.1@2025,370 2155,370 2165,380 2165,515 2180.32,530.32 U5.8@2180.32,588.46
NetR71_2: R71.2 U5.3 | length 879.3
  Top Layer w10: v2(2020,670) 2030,680 U5.3@2088.78,680
  Top Layer w15: v2(1705,370) R71.2@1775,370
  Bottom Layer w15: v2(1705,370) 1705,721.06 1728.94,745 1995,745 2020,720 v2(2020,670)
NetR72_2: R72.2 U5.6 | length 158.5
  Top Layer w10: R72.2@2025,520 2105,520 2129.13,544.13 U5.6@2129.13,588.46
NetR75_2: R75.2 U5.7 | length 271.1
  Top Layer w10: R75.2@2012.56,445 2130,445 2145,460 2145,525 2154.72,534.72 U5.7@2154.72,588.46
NetR76_1: R76.1 R77.2 U6.5 | length 156
  Top Layer w15: R77.2@3575,196.5 U6.5@3575,290.87
  Top Layer w20: R76.1@3515,192.56 3571.06,192.56 R77.2@3575,196.5
NetR81_2: R81.2 T3.6 | length 154.7
  Top Layer w25: T3.6@4380.28,1909.98 R81.2@4535,1910
NetR87_2: R87.2 U7.9 | length 173.2
  Top Layer w10: U7.9@4644.69,1178.98 4644.69,1234.69 4650,1240 4715,1240 4727.13,1252.13 R87.2@4755,1252.13
NetR95_1: R95.1 U8.1 | length 67.4
  Top Layer w15: U8.1@4790,2625 R95.1@4790,2692.44
PG2: C38.1 C69.2 D20.2 D22.2 D23.3 Q14.3 Q16.4 R41.1 R61.1 | length 3018.3
  Top Layer w15: R41.1@2055,2061.5 2093.5,2100 v1(2300,2100) ; D22.2@2513.62,720 v1(2565,720) ; v1(2550,215) 2551.81,216.81 C38.1@2551.81,290 ; R61.1@2640.32,421.5 R61.1@2640.32,429.37 ; Q16.4@2664.96,495 2640.32,470.35 R61.1@2640.32,429.37 ; Q14.3@2667.56,290 C38.1@2551.81,290 ; 2759.96,430.04 2759.29,429.37 D20.2@2710.32,429.37 R61.1@2640.32,429.37 ; C38.1@2551.81,290 2551.81,384.25 D23.3@2567.56,400 2596.93,429.37 R61.1@2640.32,429.37
  Signal Layer 2 w15: v1(2300,2100) 2330,2070 2330,770 2380,720 v1(2565,720) 2565,670 2550,655 v1(2550,215)
PR12_1: C8.1 D1.2 D36.1 Q1.5 Q1.6 Q1.7 Q1.8 Q1.9@1460,2302.5 R4.1 T1.24 | length 2025.1
  Top Layer w25: v1(1190,2035) 1192.11,2037.11 R4.1@1252.44,2037.11 ; v1(1445,2950) T1.24@1445,3052.5
  Signal Layer 1 w25: v1(1445,2950) 1445,2497.99 1460,2482.99 v1(1460,2405)
  Signal Layer 2 w25: v1(1190,2035) 1240,2085 1435,2085 1460,2110 v1(1460,2405)
  Bottom Layer w25: C8.1@807.56,2770 1265,2770 v1(1445,2950)
PR12_2: C20.1 D5.2 D40.1 Q20.5 Q20.6 Q20.7 Q20.8 Q20.9@1460.32,410.08 R20.1 T2.24 | length 2348.7
  Top Layer w20: R20.1@1252.76,144.68 1252.76,97.24 1270,80 1585,80 1605,100 1605,470 1570,505 v1(1460,505)
  Top Layer w25: v1(1445,1075) T2.24@1445,1162.5
  Signal Layer 1 w25: v1(1445,1075) 1445,608.31 1460.32,592.99 v1(1460,505)
  Bottom Layer w20: C20.1@818.05,865 v1(875,865) 1280,865 1445,1030 v1(1445,1075)
PR36_1: C9.1 D2.2 D37.1 Q3.5 Q3.6 Q3.7 Q3.8 Q3.9@1270,2302.5 R3.1 T1.21 | length 1722.8
  Top Layer w25: v1(1295,2950) T1.21@1295,3052.5 ; v1(1380,2035) 1382.11,2037.11 R3.1@1442.44,2037.11
  Signal Layer 1 w25: v1(1295,2950) 1295,2507.99 1270,2482.99 v1(1270,2405) 1270,2065 1300,2035 v1(1380,2035)
  Bottom Layer w25: C9.1@807.56,2825 1170,2825 v1(1295,2950)
PR36_2: C21.1 D6.2 D41.1 Q22.5 Q22.6 Q22.7 Q22.8 Q22.9@1270.32,410.08 R19.1 T2.21 | length 1738.8
  Top Layer w20: v1(1380,145) 1380.32,144.68 R19.1@1442.76,144.68
  Top Layer w25: v1(1295,1075) T2.21@1295,1162.5
  Signal Layer 1 w20: v1(1270,505) 1270,195 1320,145 v1(1380,145)
  Signal Layer 1 w25: v1(1270,505) 1270.32,592.99 1295,617.68 v1(1295,1075)
  Bottom Layer w20: C21.1@818.05,920 v1(925,920) 1185,920 1295,1030 v1(1295,1075)
PR45_1: C10.1 D3.2 D35.1 Q2.5 Q2.6 Q2.7 Q2.8 Q2.9@1080,2302.5 R6.1 T1.18 | length 1676.8
  Top Layer w25: v1(810,2035) 812.11,2037.11 R6.1@872.44,2037.11 ; v1(1145,2950) T1.18@1145,3052.5
  Signal Layer 1 w25: v1(810,2035) 840,2035 902.11,2097.11 1027.05,2097.11 1080,2150.06 v1(1080,2405) 1080,2482.99 1145,2547.99 v1(1145,2950)
  Bottom Layer w25: C10.1@807.56,2880 1075,2880 v1(1145,2950)
PR45_2: C22.1 D7.2 D39.1 Q21.5 Q21.6 Q21.7 Q21.8 Q21.9@1080,410.39 R22.1 T2.18 | length 1743.2
  Top Layer w20: v1(810,145) 810.32,144.68 R22.1@872.76,144.68
  Top Layer w25: v1(1145,1075) T2.18@1145,1162.5
  Signal Layer 1 w20: v1(810,145) 1030,145 1080,195 v1(1080,505)
  Signal Layer 1 w25: v1(1080,505) 1080,593.31 1145,658.31 v1(1145,1075)
  Bottom Layer w20: C22.1@817.56,975 v1(875,975) 1090,975 1145,1030 v1(1145,1075)
PR78_1: C11.1 D4.2 D38.1 Q4.5 Q4.6 Q4.7 Q4.8 Q4.9@890,2302.5 R5.1 T1.15 | length 1363.5
  Top Layer w20: v1(1000,2035) 1002.11,2037.11 R5.1@1062.44,2037.11
  Top Layer w25: v1(995,2950) T1.15@995,3052.5
  Signal Layer 1 w25: v1(890,2405) 890,2482.99 995,2587.99 v1(995,2950)
  Signal Layer 2 w20: v1(890,2405) 890,2145 v1(1000,2035)
  Bottom Layer w20: C11.1@807.56,2935 895,2935 910,2950 v1(995,2950)
PR78_2: C23.1 D8.2 D42.1 Q23.5 Q23.6 Q23.7 Q23.8 Q23.9@890.32,410.08 R21.1 T2.15 | length 1825.7
  Top Layer w20: v1(890,505) 760,505 740,485 740,95 755,80 1040,80 1062.45,102.45 R21.1@1062.45,145
  Top Layer w25: v1(995,1075) T2.15@995,1162.5
  Signal Layer 1 w25: v1(890,505) 890.32,613.82 995,718.5 v1(995,1075)
  Bottom Layer w20: C23.1@817.56,1030 950,1030 v1(995,1075)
